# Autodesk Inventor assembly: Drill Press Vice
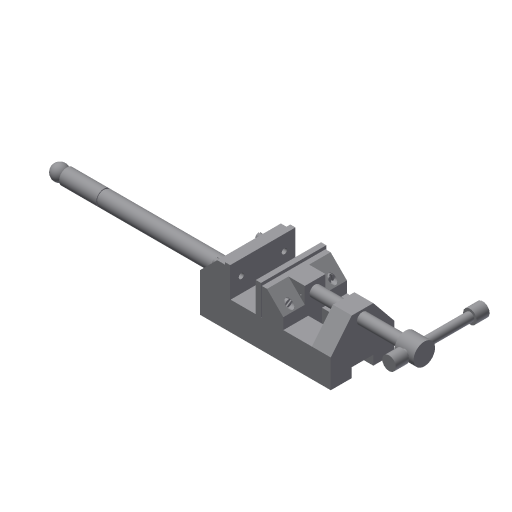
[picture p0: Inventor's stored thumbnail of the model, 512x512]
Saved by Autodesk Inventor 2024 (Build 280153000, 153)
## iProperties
Created: 2009-05
Part Number: Drill Press Vice
Document SubType Name: Assembly
Designer: Sham
Author: Sham
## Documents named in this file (9)
- D:\PROJECTS\Project 2023\RESOURCES INVENTOR 2024\RESOURCES INVENTOR 2024\Inventor_2024_tut\Inventor_2024_tut\c12_Inv_2024_tut\c12_Inv_tut_2024\c12_tut03_inv\Drill Press Vice.iam
- D:\PROJECTS\Project 2023\RESOURCES INVENTOR 2024\RESOURCES INVENTOR 2024\Inventor_2024_tut\Inventor_2024_tut\c12_Inv_2024_tut\c12_Inv_tut_2024\c12_tut03_inv\Base.ipt
- D:\PROJECTS\Project 2023\RESOURCES INVENTOR 2024\RESOURCES INVENTOR 2024\Inventor_2024_tut\Inventor_2024_tut\c12_Inv_2024_tut\c12_Inv_tut_2024\c12_tut03_inv\Safety Handle.ipt
- D:\PROJECTS\Project 2023\RESOURCES INVENTOR 2024\RESOURCES INVENTOR 2024\Inventor_2024_tut\Inventor_2024_tut\c12_Inv_2024_tut\c12_Inv_tut_2024\c12_tut03_inv\Jaw Face.ipt
- D:\PROJECTS\Project 2023\RESOURCES INVENTOR 2024\RESOURCES INVENTOR 2024\Inventor_2024_tut\Inventor_2024_tut\c12_Inv_2024_tut\c12_Inv_tut_2024\c12_tut03_inv\Movable Jaw.ipt
- D:\PROJECTS\Project 2023\RESOURCES INVENTOR 2024\RESOURCES INVENTOR 2024\Inventor_2024_tut\Inventor_2024_tut\c12_Inv_2024_tut\c12_Inv_tut_2024\c12_tut03_inv\Cap Screw.ipt
- D:\PROJECTS\Project 2023\RESOURCES INVENTOR 2024\RESOURCES INVENTOR 2024\Inventor_2024_tut\Inventor_2024_tut\c12_Inv_2024_tut\c12_Inv_tut_2024\c12_tut03_inv\Clamp Screw Handle.ipt
- D:\PROJECTS\Project 2023\RESOURCES INVENTOR 2024\RESOURCES INVENTOR 2024\Inventor_2024_tut\Inventor_2024_tut\c12_Inv_2024_tut\c12_Inv_tut_2024\c12_tut03_inv\Clamp Screw.ipt
- D:\PROJECTS\Project 2023\RESOURCES INVENTOR 2024\RESOURCES INVENTOR 2024\Inventor_2024_tut\Inventor_2024_tut\c12_Inv_2024_tut\c12_Inv_tut_2024\c12_tut03_inv\Handle Stop.ipt
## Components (13 placed, 8 different names)
1. Base:1 — Mate:2, Mate:3, Mate:7, Insert:10, Insert:11, Insert:12, Insert:13
2. Safety Handle:1
3. Jaw Face:1 — Insert:8, Insert:9, Mate:7
4. Jaw Face:2 — Insert:10, Insert:11
5. Movable Jaw:1 — Mate:2, Mate:3, Insert:2, Insert:3, Insert:4, Insert:8, Insert:9
6. Cap Screw:1 — Insert:2
7. Cap Screw:2 — Insert:3
8. Cap Screw:3 — Insert:13
9. Cap Screw:4 — Insert:12
10. Clamp Screw:1 — Insert:4, Mate:6, Rotation/Translation:2
11. Clamp Screw Handle:1 — Mate:6, Insert:5, Insert:6, Rotation/Translation:2
12. Handle Stop:1 — Insert:6, Mate:8
13. Handle Stop:2 — Insert:5
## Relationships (17: Insert 11, Mate 5, RelateRotateTranslate 1)
- Mate:2: Base:1 ↔ Movable Jaw:1
- Mate:3: Base:1 ↔ Movable Jaw:1
- Insert:2: Movable Jaw:1 ↔ Cap Screw:1
- Insert:3: Movable Jaw:1 ↔ Cap Screw:2
- Insert:4: Movable Jaw:1 ↔ Clamp Screw:1
- Mate:6: Clamp Screw:1 ↔ Clamp Screw Handle:1
- Insert:5: Clamp Screw Handle:1 ↔ Handle Stop:2
- Insert:6: Clamp Screw Handle:1 ↔ Handle Stop:1
- Insert:8: Jaw Face:1 ↔ Movable Jaw:1
- Insert:9: Jaw Face:1 ↔ Movable Jaw:1
- Mate:7: Base:1 ↔ Jaw Face:1
- Rotation/Translation:2 [RelateRotateTranslate]: Clamp Screw:1 ↔ Clamp Screw Handle:1
- Mate:8: Handle Stop:1
- Insert:10: Base:1 ↔ Jaw Face:2
- Insert:11: Base:1 ↔ Jaw Face:2
- Insert:12: Base:1 ↔ Cap Screw:4
- Insert:13: Base:1 ↔ Cap Screw:3
